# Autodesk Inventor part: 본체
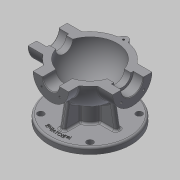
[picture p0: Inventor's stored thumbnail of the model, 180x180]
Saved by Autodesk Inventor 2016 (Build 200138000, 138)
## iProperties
Created: 2015-12
Part Number: 본체
Material: 일반
Document SubType Name: Modeling
Designer: mduedu
Density: 2.71 g/cm^3
Appearance: 기본값
Author: mduedu
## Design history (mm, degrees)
sketch "스케치1"
  geometry: L1 (-53, 0)-(53, 0); A1 r 53 centre (0, 0) between (53, 0) and (-53, 0); 2 further points
  constraints: 2 coincident, 2 end point, 2 point on circle, 1 centre point, 1 horizontal, 1 midpoint
  dimensions: "d0" = 53 radius of A1
revolve "회전1" sketch "스케치1" stored, may be unused: angle "d2" = 90 deg
feature "쉘1" dims "d11" = 10
node "작업 평면1"
sketch "스케치2"
  geometry: C1 r 31 at (0, 0); 1 further point
  constraints: 1 centre point, 1 coincident
  dimensions: "d4" = 62 diameter of C1
extrude "돌출1" join sketch "스케치2" stored distance "d5" = 10; taper "d6" = 0 deg
node "작업 평면2"
sketch "스케치3"
  geometry: C1 r 28 at (0, 0); 1 further point
  constraints: 1 centre point, 1 coincident
  dimensions: "d8" = 56 diameter of C1
extrude "돌출2" join sketch "스케치3" stored distance "d9" = 10; taper "d10" = 0 deg
hole "구멍1" diameter "d14" = 35; stored, may be unused: countersink angle "d18" = 90 deg, drill point angle "d20" = 0 deg; dims "d12" = 10, "d13" = 10, "d15" = 6, "d16" = 4, "d17" = 2, "d19" = 16
hole "구멍2" diameter "d23" = 27; stored, may be unused: countersink angle "d27" = 90 deg, drill point angle "d29" = 0 deg; dims "d21" = 10, "d22" = 10, "d24" = 6, "d25" = 4, "d26" = 2, "d28" = 16
fillet "모깎기1" dims "d30" = 0.3
hole "구멍3" diameter "d33" = 26; stored, may be unused: countersink angle "d37" = 90 deg, drill point angle "d39" = 0 deg; dims "d31" = 10, "d32" = 10, "d34" = 6, "d35" = 4, "d36" = 2, "d38" = 16
chamfer "모따기1" distance "d40" = 1; stored, may be unused: second distance "d41" = 2, angle "d42" = 45 deg
sketch "스케치4"
  geometry: L1 (0, 0)-(0, -25); L2 (0, 0)-(-17.678, -17.678); A1 r 25 centre (0, 0) between (-17.678, -17.678) and (0, -25); 1 further point
  constraints: 4 end point, 2 point on circle, 1 centre point, 1 coincident, 1 vertical
  dimensions: "d43" = 50 diameter of A1; "d47" = 45 deg angle of L1 L2
hole "구멍4" sketch "스케치4" at (-17.678, -17.678) diameter "d49" = 3.242; stored, may be unused: countersink angle "d53" = 90 deg, drill point angle "d55" = 118 deg; dims "d50" = 11, "d51" = 4, "d52" = 2, "d54" = 13
sketch "스케치5"
  geometry: L1 (0, 0)-(0, -20); L2 (0, 0)-(-14.142, -14.142); A1 r 20 centre (0, 0) between (0, -20) and (-14.142, -14.142); 2 further points
  constraints: 4 end point, 2 coincident, 2 point on circle, 1 centre point, 1 vertical
  dimensions: "d59" = 40 diameter of A1; "d65" = 45 deg angle of L1 L2
hole "구멍5" sketch "스케치5" at (-14.142, -14.142) diameter "d67" = 3.242; stored, may be unused: countersink angle "d71" = 90 deg, drill point angle "d73" = 118 deg; dims "d68" = 8, "d69" = 4, "d70" = 2, "d72" = 10
node "작업 평면3"
sketch "스케치6"
  geometry: C1 r 65 at (0, 0); 1 further point
  constraints: 1 centre point, 1 coincident
  dimensions: "d78" = 130 diameter of C1
extrude "돌출3" join sketch "스케치6" distance "d80" = 10; taper "d81" = 0 deg
sketch "스케치7"
  geometry: C1 r 20 at (0, 0); 1 further point
  constraints: 1 centre point, 1 coincident
  dimensions: "d82" = 40 diameter of C1
extrude "돌출4" join sketch "스케치7" stored distance "d84" = 10; taper "d85" = 0 deg
sketch "스케치8"
  geometry: 2 further points
  constraints: 1 coincident
hole "구멍6" sketch "스케치8" at (0, 0) diameter "d86" = 20; stored, may be unused: countersink angle "d90" = 90 deg, drill point angle "d92" = 118 deg; dims "d87" = 7, "d88" = 40, "d89" = 5, "d91" = 10
fillet "모깎기2" dims "d93" = 0.3
sketch "스케치9"
  geometry: L1 (65, -75)-(-65, -75) reference; L2 (-45, -75)-(-38.245, -36.692); A1 r 53 centre (0, 0) between (42.988, 31) and (42.988, -31) reference; 1 further point
  constraints: 2 end point, 1 point on circle, 1 point on line
  dimensions: "d94" = 45 horizontal distance of L2.start point (0, 0); "d95" = 80 deg angle of L2 L1
feature "리브1" sketch "스케치9" dims "d96" = 1, "d97" = 8, "d98" = 0, "d99" = 0, "d100" = 1, "d101" = 1
sketch "스케치10"
  geometry: L1 (0, 0)-(0, -55); L2 (0, 0)-(-38.891, -38.891); A1 r 55 centre (0, 0) between (0, -55) and (-38.891, -38.891); 2 further points
  constraints: 4 end point, 2 coincident, 2 point on circle, 1 centre point, 1 vertical
  dimensions: "d105" = 110 diameter of A1; "d107" = 45 deg angle of L1 L2
hole "구멍7" sketch "스케치10" at (-38.891, -38.891) diameter "d109" = 10; stored, may be unused: countersink angle "d113" = 90 deg, drill point angle "d115" = 118 deg; dims "d110" = 7, "d111" = 40, "d112" = 5, "d114" = 10
fillet "모깎기3" dims "d120" = 3
fillet "모깎기4" dims "d121" = 3, "d122" = 3
fillet "모깎기5" dims "d123" = 3
fillet "모깎기6" dims "d124" = 3
sketch "스케치11"
  geometry: C1 r 5 at (-38.891, 38.891) reference; C2 r 5 at (38.891, 38.891) reference; C3 r 5 at (38.891, -38.891) reference; C4 r 5 at (-38.891, -38.891) reference; C5 r 20 at (0, 0) reference; C6 r 65 at (0, 0) reference; 1 further point
  constraints: 3 other
feature "엠보싱1" sketch "스케치11" dims "d125" = 0.5, "d126" = 0
sketch "스케치12"
  geometry: L1 (0, 100)-(0, -100); L2 (0, 100)-(100, 100); L3 (100, 100)-(100, -100); L4 (100, -100)-(0, -100); 2 further points
  constraints: 8 end point, 3 perpendicular, 1 coincident, 1 midpoint, 1 vertical
  dimensions: "d127" = 200 distance of L2.end L3.end; "d129" = 100 distance between parallel lines of L1 L3
extrude "돌출5" cut sketch "스케치12" stored distance "d130" = 10; taper "d131" = 0 deg
sketch "스케치13"
  geometry: C1 r 7 at (0, 53); A1 r 53 centre (0, 0) between (42.113, 32.179) and (-42.113, 32.179) reference; 1 further point
  constraints: 1 centre point, 1 point on circle
  dimensions: "d132" = 14 diameter of C1
extrude "돌출6" join sketch "스케치13" distance "d134" = 15; taper "d135" = 0 deg
hole "구멍8" diameter "d139" = 3.242; stored, may be unused: countersink angle "d143" = 90 deg, drill point angle "d145" = 118 deg; dims "d140" = 8, "d141" = 4, "d142" = 2, "d144" = 10, "d148" = 10, "d149" = 10
fillet "모깎기7" dims "d146" = 3
fillet "모깎기8" dims "d147" = 3
node "솔리드1"
mirror "대칭1"
mirror "대칭2"
pattern_circular "원형 패턴1" dims angle "d57" = 360 deg
mirror "대칭3"
pattern_circular "원형 패턴2" dims angle "d75" = 360 deg
pattern_circular "원형 패턴3" dims angle "d103" = 360 deg
pattern_circular "원형 패턴4" dims angle "d118" = 360 deg
node "투영된 루프1"
other parameters: "d3" = 67, "d7" = 62, "d77" = -85
